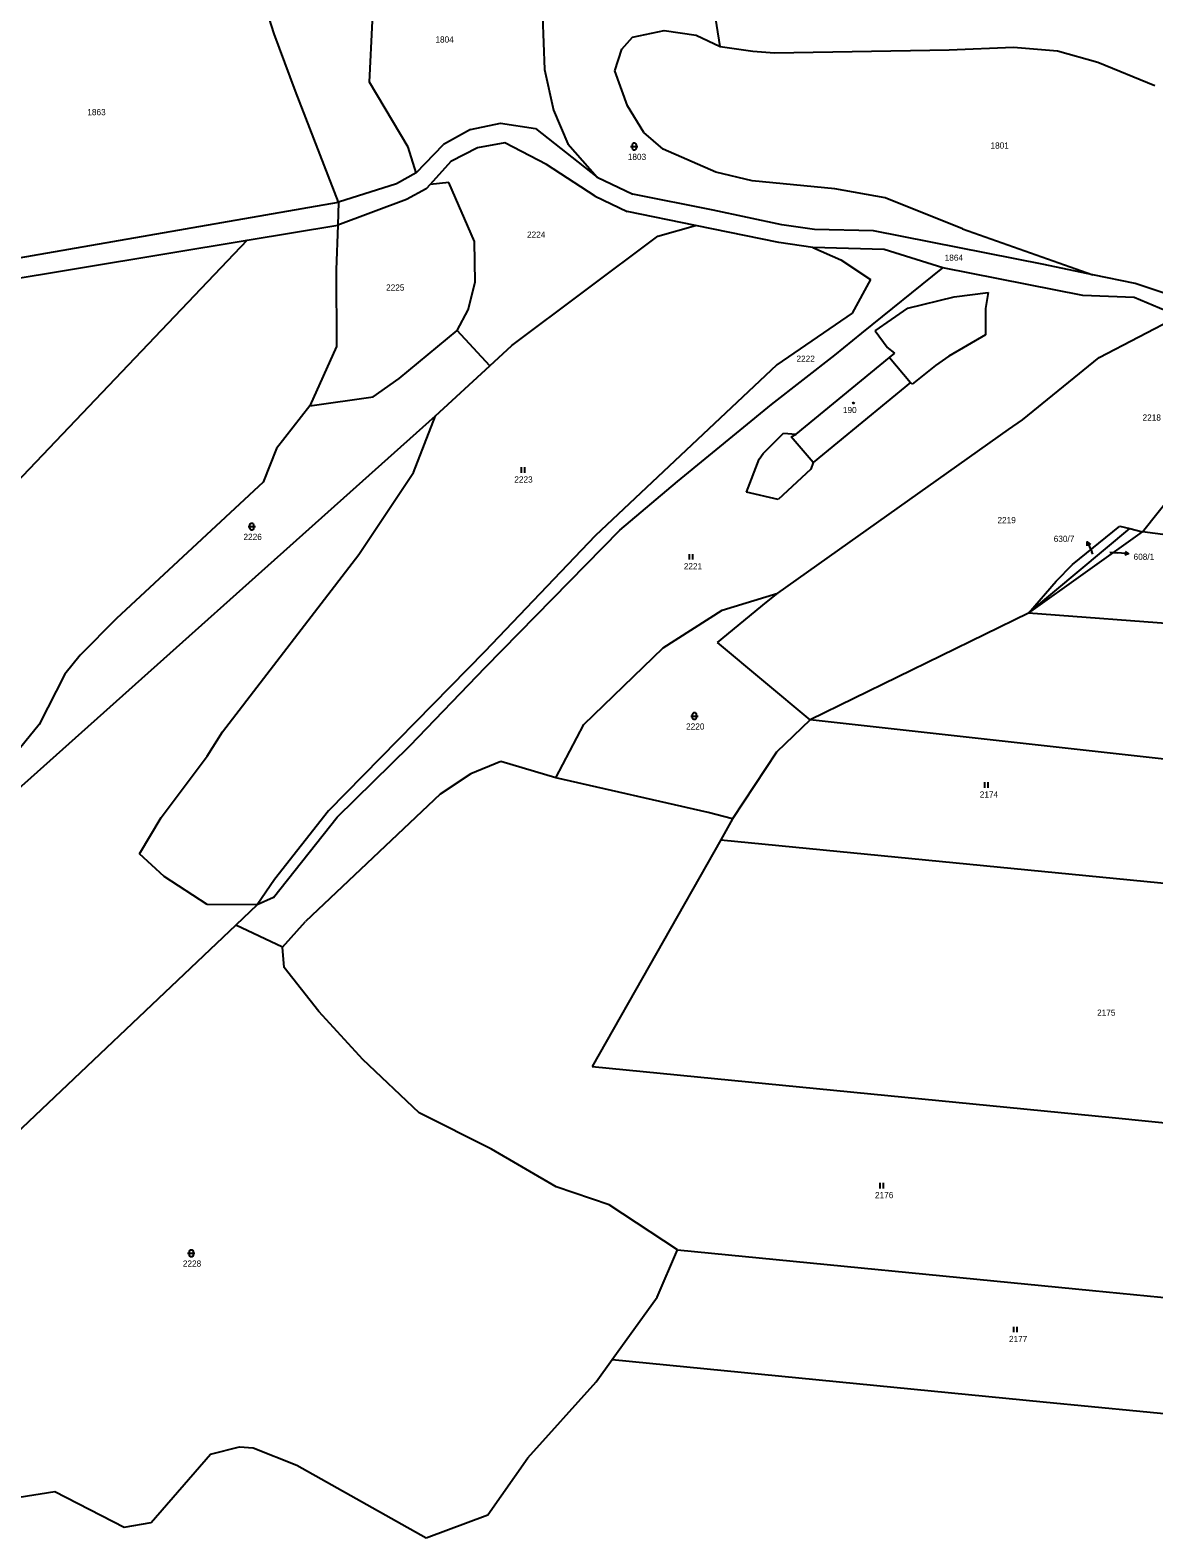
# Model space of a CAD drawing. Extents: x -802857 to -799647, y -1020285 to -1015884.
# Drawn here: x -802140.5 to -801830.8, y -1018068.1 to -1017652.7 of the extents above; entities that cross this region are included whole.
import ezdxf

# ---------------------------------------------------------------- set-up
doc = ezdxf.new("R2010")
doc.units = 0
for name, color, linetype in [('Default', 7, 'Continuous'), ('KN_HRANICE', 7, 'Continuous'), ('KN_KULTURY', 7, 'Continuous'), ('KN_PARCELY', 7, 'Continuous'), ('KN_SLUCKY', 7, 'Continuous')]:
    doc.layers.add(name, color=color, linetype=linetype)

# ---------------------------------------------------------------- blocks, each defined once
blk = doc.blocks.new('306')
at = {"layer": 'Default'}
for p, q in [((-0.5, 1.5), (-0.5, 0)), ((0.5, 0), (0.5, 1.5))]:
    blk.add_line(p, q, dxfattribs=at)
blk = doc.blocks.new('316')
at = {"layer": 'Default'}
for points in [[(-1, 1), (0.27, 1), (1, 1)], [(-0.5, 1.5), (-0.4, 1.79), (-0.15, 1.97), (0.16, 1.97), (0.41, 1.79), (0.51, 1.5), (0.51, 0.5), (0.41, 0.21), (0.16, 0.03), (-0.15, 0.03), (-0.4, 0.21), (-0.5, 0.5), (-0.5, 1.5)]]:
    blk.add_lwpolyline(points, dxfattribs=at)
blk = doc.blocks.new('10292')
at = {"layer": 'Default'}
blk.add_line((0, 3), (0, 0), dxfattribs=at)
blk.add_lwpolyline([(-0.5, 2), (0, 3), (0.5, 2)], dxfattribs=at)
blk = doc.blocks.new('402')
at = {"layer": 'Default'}
blk.add_lwpolyline([(0.09, 0.15), (0.18, 0), (0.09, -0.15), (-0.09, -0.15), (-0.18, 0), (-0.09, 0.15), (0.09, 0.15)], dxfattribs=at)

msp = doc.modelspace()

# ---------------------------------------------------------------- linework, layer by layer
at = {"layer": 'KN_HRANICE'}
for p, q in [((-802073.29, -1017653.73), (-802077.76, -1017639.34)), ((-801950.38, -1017657.2), (-801952.94, -1017640.64)), ((-802046.96, -1017667.05), (-802046.13, -1017650.15)), ((-801999.28, -1017648.83), (-801998.77, -1017663.53)), ((-802067.34, -1017669.51), (-802073.29, -1017653.73)), ((-801977.44, -1017657.9), (-801974.49, -1017654.58)), ((-801974.49, -1017654.58), (-801965.75, -1017652.74)), ((-801965.75, -1017652.74), (-801956.95, -1017654.02)), ((-801956.95, -1017654.02), (-801950.38, -1017657.2)), ((-801979.4, -1017663.93), (-801977.44, -1017657.9)), ((-801950.38, -1017657.2), (-801941.33, -1017658.45)), ((-801941.33, -1017658.45), (-801935.37, -1017658.91)), ((-801935.37, -1017658.91), (-801887.2, -1017658.08)), ((-801887.2, -1017658.08), (-801869.47, -1017657.34)), ((-801869.47, -1017657.34), (-801857.37, -1017658.37)), ((-801857.37, -1017658.37), (-801846.23, -1017661.47)), ((-801998.77, -1017663.53), (-801996.3, -1017674.68)), ((-801975.85, -1017673.52), (-801979.4, -1017663.93)), ((-801846.23, -1017661.47), (-801830.59, -1017667.95)), ((-802036.31, -1017684.9), (-802046.96, -1017667.05)), ((-802055.5, -1017700.07), (-802067.34, -1017669.51)), ((-801996.3, -1017674.68), (-801992.33, -1017684.03)), ((-801971.39, -1017680.92), (-801975.85, -1017673.52)), ((-802019.18, -1017680.06), (-802026.57, -1017684.21)), ((-802019.18, -1017680.06), (-802010.9, -1017678.28)), ((-802010.9, -1017678.28), (-802001.19, -1017679.74)), ((-802001.19, -1017679.74), (-801984.22, -1017693.14)), ((-801966.06, -1017685.51), (-801971.39, -1017680.92)), ((-802034.1, -1017691.96), (-802036.31, -1017684.9)), ((-802034.1, -1017691.96), (-802026.57, -1017684.21)), ((-802017.23, -1017685.07), (-802024.59, -1017688.88)), ((-802009.72, -1017683.69), (-802017.23, -1017685.07)), ((-801998.21, -1017689.66), (-802009.72, -1017683.69)), ((-801992.33, -1017684.03), (-801984.22, -1017693.14)), ((-801951.55, -1017691.84), (-801966.06, -1017685.51)), ((-802024.59, -1017688.88), (-802030.26, -1017695.18)), ((-801984.79, -1017698.41), (-801998.21, -1017689.66)), ((-802034.1, -1017691.96), (-802039.55, -1017694.99)), ((-801984.22, -1017693.14), (-801974.42, -1017697.82)), ((-801941.49, -1017694.19), (-801951.55, -1017691.84)), ((-802039.55, -1017694.99), (-802055.5, -1017700.07)), ((-802031.37, -1017696.41), (-802036.75, -1017699.36)), ((-802030.26, -1017695.18), (-802031.37, -1017696.41)), ((-802025.1, -1017694.66), (-802030.26, -1017695.18)), ((-802018.03, -1017710.92), (-802025.1, -1017694.66)), ((-801952.31, -1017702.28), (-801974.42, -1017697.82)), ((-801918.73, -1017696.42), (-801941.49, -1017694.19)), ((-801904.91, -1017698.89), (-801918.73, -1017696.42)), ((-802214.72, -1017727.85), (-802055.5, -1017700.07)), ((-802036.75, -1017699.36), (-802055.74, -1017706.41)), ((-802055.5, -1017700.07), (-802055.74, -1017706.41)), ((-801984.79, -1017698.41), (-801976.01, -1017702.6)), ((-801883.57, -1017707.38), (-801904.91, -1017698.89)), ((-801957.11, -1017706.49), (-801976.01, -1017702.6)), ((-801933.35, -1017706.28), (-801952.31, -1017702.28)), ((-801924.35, -1017707.57), (-801933.35, -1017706.28)), ((-802080.71, -1017710.54), (-802055.74, -1017706.41)), ((-802055.74, -1017706.41), (-802056.21, -1017718.73)), ((-802007.79, -1017739.54), (-801967.49, -1017709.46)), ((-801967.49, -1017709.46), (-801957.11, -1017706.49)), ((-801934.14, -1017711.22), (-801957.11, -1017706.49)), ((-801908.05, -1017707.99), (-801924.35, -1017707.57)), ((-801861.12, -1017717.28), (-801908.05, -1017707.99)), ((-801883.57, -1017707.38), (-801847.66, -1017720.08)), ((-802165.66, -1017724.61), (-802080.71, -1017710.54)), ((-802080.71, -1017710.54), (-802160.03, -1017793.81)), ((-802017.84, -1017722.15), (-802018.03, -1017710.92)), ((-801924.8, -1017712.56), (-801934.14, -1017711.22)), ((-801905.16, -1017713.07), (-801924.8, -1017712.56)), ((-801924.8, -1017712.56), (-801917.11, -1017715.95)), ((-801888.93, -1017718.16), (-801905.16, -1017713.07)), ((-802056.21, -1017718.73), (-802056.08, -1017739.79)), ((-801917.11, -1017715.95), (-801908.93, -1017721.34)), ((-801911.34, -1017736.13), (-801888.93, -1017718.16)), ((-801850.39, -1017725.77), (-801888.93, -1017718.16)), ((-801847.66, -1017720.08), (-801861.12, -1017717.28)), ((-802019.79, -1017729.73), (-802017.84, -1017722.15)), ((-801908.93, -1017721.34), (-801913.97, -1017730.65)), ((-801835.95, -1017722.51), (-801847.66, -1017720.08)), ((-801811.36, -1017730.69), (-801835.95, -1017722.51)), ((-801898.63, -1017729.29), (-801885.89, -1017726.13)), ((-801885.89, -1017726.13), (-801876.45, -1017724.99)), ((-801876.45, -1017724.99), (-801877.23, -1017729.41)), ((-801836.26, -1017726.37), (-801850.39, -1017725.77)), ((-801824.02, -1017731.49), (-801836.26, -1017726.37)), ((-802022.78, -1017735.45), (-802019.79, -1017729.73)), ((-801913.97, -1017730.65), (-801934.74, -1017744.89)), ((-801907.59, -1017735.52), (-801898.63, -1017729.29)), ((-801877.23, -1017729.41), (-801877.23, -1017736.62)), ((-801845.86, -1017742.83), (-801824.02, -1017731.49)), ((-802038.85, -1017748.66), (-802022.78, -1017735.45)), ((-802013.84, -1017745.13), (-802022.78, -1017735.45)), ((-802013.84, -1017745.13), (-802007.79, -1017739.54)), ((-801918.76, -1017742.21), (-801911.34, -1017736.13)), ((-801907.59, -1017735.52), (-801904.35, -1017739.98)), ((-801877.23, -1017736.62), (-801887.3, -1017742.49)), ((-802056.08, -1017739.79), (-802063.46, -1017756.18)), ((-801936.15, -1017755.85), (-801918.76, -1017742.21)), ((-801929.37, -1017763.94), (-801903.63, -1017742.86)), ((-801902.18, -1017741.64), (-801904.35, -1017739.98)), ((-801903.63, -1017742.86), (-801902.18, -1017741.64)), ((-801887.3, -1017742.49), (-801890.99, -1017745.1)), ((-801867.04, -1017760.04), (-801845.86, -1017742.83)), ((-802028.78, -1017758.92), (-802013.84, -1017745.13)), ((-801934.74, -1017744.89), (-801984.76, -1017792.02)), ((-801890.99, -1017745.1), (-801897.41, -1017750.25)), ((-802045.97, -1017753.74), (-802038.85, -1017748.66)), ((-801897.85, -1017749.75), (-801924.67, -1017771.76)), ((-801897.41, -1017750.25), (-801897.85, -1017749.75)), ((-802063.46, -1017756.18), (-802072.62, -1017767.89)), ((-802063.46, -1017756.18), (-802045.97, -1017753.74)), ((-801962.1, -1017777), (-801936.15, -1017755.85)), ((-802158.81, -1017875.07), (-802028.78, -1017758.92)), ((-802034.86, -1017774.54), (-802028.78, -1017758.92)), ((-801870.84, -1017762.72), (-801867.04, -1017760.04)), ((-801938.53, -1017769.27), (-801932.86, -1017763.71)), ((-801934.42, -1017807.77), (-801870.84, -1017762.72)), ((-801932.86, -1017763.71), (-801929.37, -1017763.94)), ((-802072.62, -1017767.89), (-802076.29, -1017777.2)), ((-801943.08, -1017779.96), (-801939.63, -1017770.91)), ((-801939.63, -1017770.91), (-801938.53, -1017769.27)), ((-801924.67, -1017771.76), (-801925.36, -1017773.65)), ((-801833.92, -1017790.89), (-801817.75, -1017770.54)), ((-802049.96, -1017797.11), (-802034.86, -1017774.54)), ((-801925.36, -1017773.65), (-801934.33, -1017781.96)), ((-802076.29, -1017777.2), (-802116.69, -1017814.77)), ((-801977.95, -1017790.39), (-801962.1, -1017777)), ((-801934.33, -1017781.96), (-801943.08, -1017779.96)), ((-801853.23, -1017799.91), (-801840.23, -1017789.32)), ((-801840.23, -1017789.32), (-801837.45, -1017790.01)), ((-801984.76, -1017792.02), (-802015.22, -1017823.87)), ((-802014.99, -1017828.2), (-801977.95, -1017790.39)), ((-801865.33, -1017813.26), (-801837.45, -1017790.01)), ((-801865.33, -1017813.26), (-801833.92, -1017790.89)), ((-801837.45, -1017790.01), (-801833.92, -1017790.89)), ((-801804.79, -1017794.82), (-801833.92, -1017790.89)), ((-802087.46, -1017845.97), (-802049.96, -1017797.11)), ((-801857.78, -1017804.52), (-801853.23, -1017799.91)), ((-801865.33, -1017813.26), (-801857.78, -1017804.52)), ((-801949.78, -1017812.5), (-801934.42, -1017807.77)), ((-801937.57, -1017810.25), (-801934.42, -1017807.77)), ((-801966.06, -1017822.88), (-801949.78, -1017812.5)), ((-801951.09, -1017821.36), (-801937.57, -1017810.25)), ((-801865.33, -1017813.26), (-801925.58, -1017842.7)), ((-801804.26, -1017817.96), (-801865.33, -1017813.26)), ((-802116.69, -1017814.77), (-802126.72, -1017824.88)), ((-801925.58, -1017842.7), (-801951.09, -1017821.36)), ((-802126.72, -1017824.88), (-802130.98, -1017830.1)), ((-802015.22, -1017823.87), (-802058.24, -1017867.75)), ((-801987.9, -1017843.99), (-801966.06, -1017822.88)), ((-802130.98, -1017830.1), (-802137.99, -1017843.97)), ((-802035.83, -1017849.88), (-802014.99, -1017828.2)), ((-801925.58, -1017842.7), (-801934.85, -1017851.61)), ((-801807.02, -1017855.84), (-801925.58, -1017842.7)), ((-802137.99, -1017843.97), (-802154.31, -1017863.96)), ((-802091.75, -1017852.68), (-802087.46, -1017845.97)), ((-801995.67, -1017858.67), (-801987.9, -1017843.99)), ((-802055.92, -1017869.51), (-802035.83, -1017849.88)), ((-801934.85, -1017851.61), (-801946.92, -1017869.96)), ((-802104.41, -1017869.62), (-802091.75, -1017852.68)), ((-802010.81, -1017854.15), (-802019.02, -1017857.54)), ((-801995.67, -1017858.67), (-802010.81, -1017854.15)), ((-802019.02, -1017857.54), (-802027.52, -1017863.19)), ((-801953.68, -1017868.25), (-801995.67, -1017858.67)), ((-802027.52, -1017863.19), (-802064.59, -1017898.25)), ((-802058.24, -1017867.75), (-802073.14, -1017886.68)), ((-801946.92, -1017869.96), (-801953.68, -1017868.25)), ((-802110.38, -1017879.63), (-802104.41, -1017869.62)), ((-802073.43, -1017891.65), (-802055.92, -1017869.51)), ((-801946.92, -1017869.96), (-801950.19, -1017875.73)), ((-801950.19, -1017875.73), (-801985.62, -1017938.22)), ((-801950.19, -1017875.73), (-801810.65, -1017889.4)), ((-802103.58, -1017885.82), (-802110.38, -1017879.63)), ((-802091.71, -1017893.55), (-802103.58, -1017885.82)), ((-802073.14, -1017886.68), (-802077.91, -1017893.64)), ((-802073.43, -1017891.65), (-802077.91, -1017893.64)), ((-802077.91, -1017893.64), (-802091.71, -1017893.55)), ((-802077.91, -1017893.64), (-802083.83, -1017899.25)), ((-802083.83, -1017899.25), (-802208.45, -1018017.4)), ((-802070.99, -1017905.36), (-802083.83, -1017899.25)), ((-802070.99, -1017905.36), (-802064.59, -1017898.25)), ((-802070.54, -1017910.89), (-802070.99, -1017905.36)), ((-802060.92, -1017923.04), (-802070.54, -1017910.89)), ((-802048.85, -1017936.25), (-802060.92, -1017923.04)), ((-802033.28, -1017950.98), (-802048.85, -1017936.25)), ((-801985.62, -1017938.22), (-801842.31, -1017952.29)), ((-802013.35, -1017960.99), (-802033.28, -1017950.98)), ((-801842.31, -1017952.29), (-801720.64, -1017964.21)), ((-801995.53, -1017971.39), (-802013.35, -1017960.99)), ((-801980.94, -1017976.3), (-801995.53, -1017971.39)), ((-801962.14, -1017988.67), (-801980.94, -1017976.3)), ((-801967.67, -1018001.73), (-801962.14, -1017988.67)), ((-801962.14, -1017988.67), (-801847.73, -1017999.9)), ((-801847.73, -1017999.9), (-801736.86, -1018010.79)), ((-801980.07, -1018018.89), (-801967.67, -1018001.73)), ((-801984.53, -1018025.08), (-801980.07, -1018018.89)), ((-801980.07, -1018018.89), (-801861.32, -1018030.55)), ((-802003.32, -1018046.02), (-801984.53, -1018025.08)), ((-801861.32, -1018030.55), (-801747.41, -1018041.74)), ((-802107.18, -1018063.86), (-802090.78, -1018045)), ((-802090.78, -1018045), (-802082.79, -1018042.96)), ((-802082.79, -1018042.96), (-802079.09, -1018043.24)), ((-802079.09, -1018043.24), (-802067.02, -1018047.99)), ((-802014.35, -1018061.69), (-802003.32, -1018046.02)), ((-802067.02, -1018047.99), (-802031.36, -1018068.05)), ((-802143.56, -1018056.86), (-802133.71, -1018055.27)), ((-802133.71, -1018055.27), (-802114.64, -1018065.07)), ((-802031.36, -1018068.05), (-802014.35, -1018061.69)), ((-802114.64, -1018065.07), (-802107.18, -1018063.86))]:
    msp.add_line(p, q, dxfattribs=at)
at = {"layer": 'KN_PARCELY'}
for p, q in [((-801847.68, -1017797), (-801847.95, -1017796.4)), ((-801842.94, -1017796.47), (-801840.75, -1017796.66))]:
    msp.add_line(p, q, dxfattribs=at)
at = {"layer": 'KN_SLUCKY'}
for p, q in [((-801903.63, -1017742.86), (-801897.85, -1017749.75)), ((-801930.75, -1017764.7), (-801929.37, -1017763.94)), ((-801924.67, -1017771.76), (-801930.75, -1017764.7))]:
    msp.add_line(p, q, dxfattribs=at)

# ---------------------------------------------------------------- block references
at = {"layer": 'KN_KULTURY'}
for name, p in [('316', (-801974.04, -1017685.73)), ('402', (-801913.56, -1017755.43)), ('306', (-802004.71, -1017774.61)), ('316', (-802079.42, -1017790.43)), ('306', (-801958.39, -1017798.53)), ('316', (-801957.42, -1017842.67)), ('306', (-801876.98, -1017861.4)), ('306', (-801905.86, -1017971.77)), ('316', (-802096.12, -1017990.64)), ('306', (-801868.97, -1018011.41))]:
    msp.add_blockref(name, p, dxfattribs=at)
at = {"layer": 'KN_PARCELY'}
for p, rotation in [((-801847.95, -1017796.4), 24.064226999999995), ((-801840.75, -1017796.66), -94.835132)]:
    msp.add_blockref('10292', p, dxfattribs=dict(at, rotation=rotation))

# ---------------------------------------------------------------- texts
for s, height, p in [('1804', 1.7, (-802028.81, -1017656.1)), ('1863', 1.7, (-802124.75, -1017676.11)), ('1801', 1.7, (-801875.83, -1017685.31)), ('1803', 1.7, (-801975.8, -1017688.43)), ('2224', 1.7, (-802003.57, -1017709.87)), ('1864', 1.7, (-801888.47, -1017716.22)), ('2225', 1.7, (-802042.41, -1017724.44)), ('2222', 1.7, (-801929.31, -1017744.04)), ('190', 1.7, (-801916.52, -1017758.18)), ('2218', 1.7, (-801833.93, -1017760.25)), ('2223', 1.7, (-802007.07, -1017777.31)), ('2219', 1.7, (-801873.91, -1017788.51)), ('2226', 1.7, (-802081.71, -1017793.13)), ('630/7', 1.7, (-801858.42, -1017793.66)), ('630/7', 0.1, (-801847.93, -1017797)), ('608/1', 0.1, (-801843.17, -1017796.47)), ('608/1', 1.7, (-801836.4, -1017798.61)), ('2221', 1.7, (-801960.37, -1017801.23)), ('2220', 1.7, (-801959.73, -1017845.37)), ('2174', 1.7, (-801878.79, -1017864.1)), ('2175', 1.7, (-801846.46, -1017924.21)), ('2176', 1.7, (-801907.67, -1017974.47)), ('2228', 1.7, (-802098.42, -1017993.34)), ('2177', 1.7, (-801870.75, -1018014.11))]:
    msp.add_text(s, height=height, dxfattribs=at).set_placement(p)

doc.saveas('drawing.dxf')
